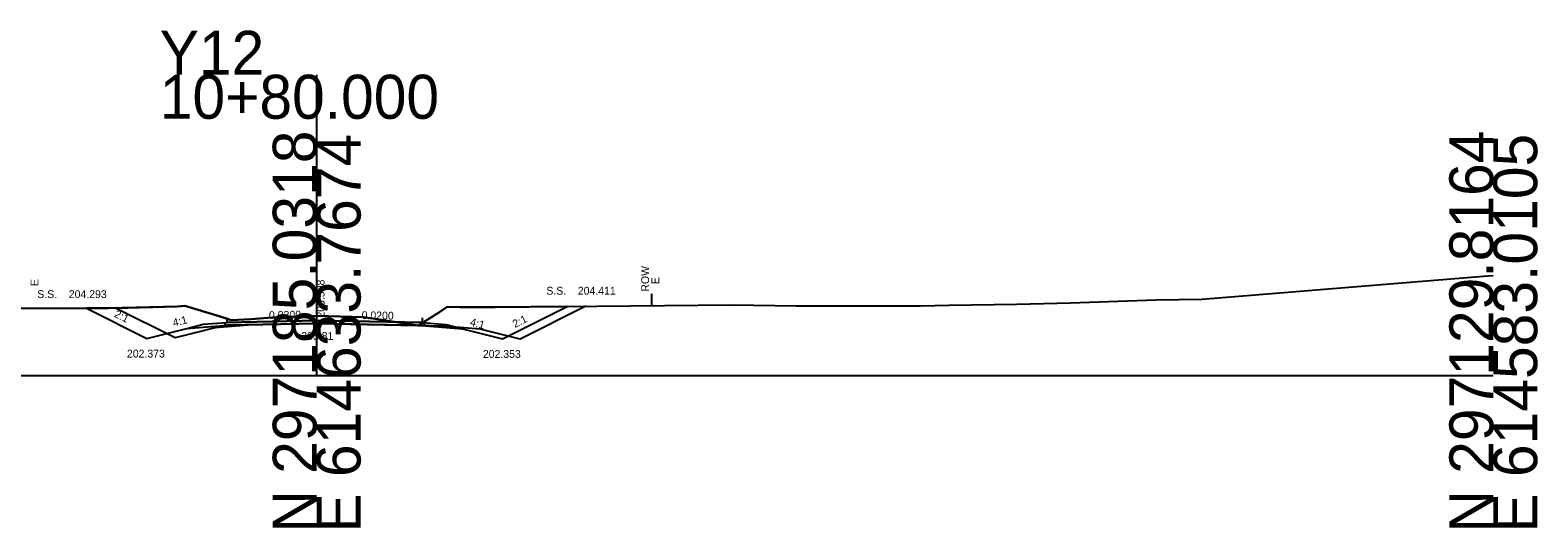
# Model space of a CAD drawing. Extents: x 517327 to 517505, y 114839 to 117367.
# Drawn here: x 517409.1 to 517505.2, y 116838.7 to 116870.4 of the extents above; entities that cross this region are included whole.
import ezdxf

# ---------------------------------------------------------------- set-up
doc = ezdxf.new("R2010")
doc.units = 0
for name, color, linetype in [('Exist XS Ground Line', 7, 'Continuous'), ('Old_Level_3', 7, 'Continuous'), ('Old_Level_5', 7, 'Continuous'), ('Old_Level_59', 7, 'Continuous'), ('Old_Level_63', 7, 'Continuous'), ('Prop XS Dump Level', 7, 'Continuous'), ('Prop XS Earthwork Shape', 7, 'Continuous'), ('Prop XS Elevation Labels', 7, 'Continuous'), ('Prop XS EOT Tick Mark', 7, 'Continuous'), ('Prop XS Exc Vertical Line 1', 7, 'Continuous'), ('Prop XS Exc Vertical Line 2', 7, 'Continuous'), ('Prop XS Finish Grade', 7, 'Continuous'), ('Prop XS Finish Grade Earthwork', 7, 'Continuous'), ('Prop XS Finish Grade Pavement', 7, 'Continuous'), ('Prop XS Hydro Elevations', 7, 'Continuous'), ('Prop XS Pvmt Edge Slope', 7, 'Continuous'), ('Prop XS Side Slope Text', 7, 'Continuous'), ('Prop XS Subgrade Earthwork', 7, 'Continuous'), ('Prop XS Suitable Common Exc Shape', 7, 'Continuous')]:
    doc.layers.add(name, color=color, linetype=linetype)

msp = doc.modelspace()

# ---------------------------------------------------------------- linework, layer by layer
at = {"layer": 'Exist XS Ground Line'}
for p, q in [((517483.816, 116853.243), (517501.736, 116854.705)), ((517501.736, 116854.705), (517502.365, 116854.751)), ((517471.995, 116852.914), (517475.409, 116853.002)), ((517475.409, 116853.002), (517480.879, 116853.183)), ((517480.879, 116853.183), (517483.816, 116853.243)), ((517404.83, 116852.668), (517414.081, 116852.656)), ((517414.081, 116852.656), (517418.494, 116852.776)), ((517418.494, 116852.776), (517418.955, 116852.803)), ((517418.955, 116852.803), (517421.159, 116852.154)), ((517421.159, 116852.154), (517421.913, 116851.895)), ((517421.913, 116851.895), (517423.177, 116851.971)), ((517423.177, 116851.971), (517424.538, 116852.068)), ((517424.538, 116852.068), (517426.792, 116852.151)), ((517426.792, 116852.151), (517427.456, 116852.176)), ((517427.456, 116852.176), (517428.114, 116852.159)), ((517428.114, 116852.159), (517430.36, 116852.093)), ((517430.36, 116852.093), (517431.779, 116851.873)), ((517433.833, 116851.562), (517435.188, 116852.414)), ((517435.188, 116852.414), (517435.691, 116852.74)), ((517435.691, 116852.74), (517436.514, 116852.716)), ((517436.514, 116852.716), (517438.736, 116852.734)), ((517438.736, 116852.734), (517453.851, 116852.871)), ((517453.851, 116852.871), (517457.919, 116852.819)), ((517457.919, 116852.819), (517465.86, 116852.803)), ((517465.86, 116852.803), (517467.658, 116852.851)), ((517467.658, 116852.851), (517471.995, 116852.914)), ((517431.779, 116851.873), (517433.833, 116851.562))]:
    msp.add_line(p, q, dxfattribs=at)
at = {"layer": 'Old_Level_63'}
for p, q in [((517427.365, 116848.365), (517427.365, 116867.524)), ((517352.365, 116848.365), (517427.365, 116848.365)), ((517427.365, 116848.365), (517502.365, 116848.365))]:
    msp.add_line(p, q, dxfattribs=at)
at = {"layer": 'Prop XS Dump Level'}
for p, q in [((517421.631, 116851.758), (517427.365, 116851.873)), ((517427.365, 116851.873), (517434.119, 116851.738))]:
    msp.add_line(p, q, dxfattribs=at)
at = {"layer": 'Prop XS Earthwork Shape'}
for points in [[(517412.692, 116852.658), (517416.531, 116850.738), (517419.082, 116851.376), (517420.131, 116851.46), (517421.437, 116851.564), (517421.631, 116851.568), (517427.365, 116851.683), (517433.833, 116851.562), (517431.779, 116851.873), (517430.36, 116852.093), (517428.114, 116852.159), (517427.456, 116852.176), (517426.792, 116852.151), (517424.538, 116852.068), (517423.177, 116851.971), (517421.913, 116851.895), (517421.159, 116852.154), (517418.955, 116852.803), (517418.494, 116852.776), (517414.081, 116852.656)], [(517436.668, 116851.355), (517439.219, 116850.718), (517443.335, 116852.776), (517438.736, 116852.734), (517436.514, 116852.716), (517435.691, 116852.74), (517435.188, 116852.414), (517433.833, 116851.562), (517434.119, 116851.548), (517434.313, 116851.544), (517435.619, 116851.439)]]:
    msp.add_lwpolyline(points, close=True, dxfattribs=at)
at = {"layer": 'Prop XS EOT Tick Mark'}
for p, q in [((517421.631, 116852.063), (517421.631, 116851.758)), ((517434.119, 116851.738), (517434.119, 116852.042))]:
    msp.add_line(p, q, dxfattribs=at)
at = {"layer": 'Prop XS Exc Vertical Line 1'}
msp.add_line((517448.701, 116853.574), (517448.701, 116852.824), dxfattribs=at)
at = {"layer": 'Prop XS Exc Vertical Line 2'}
msp.add_line((517448.701, 116853.574), (517448.701, 116852.824), dxfattribs=at)
at = {"layer": 'Prop XS Finish Grade'}
for p, q in [((517419.082, 116851.376), (517420.131, 116851.638)), ((517420.131, 116851.638), (517421.631, 116851.758)), ((517434.119, 116851.738), (517435.619, 116851.618)), ((517435.619, 116851.618), (517436.668, 116851.355))]:
    msp.add_line(p, q, dxfattribs=at)
at = {"layer": 'Prop XS Finish Grade Earthwork'}
for p, q in [((517412.692, 116852.658), (517416.531, 116850.738)), ((517439.219, 116850.718), (517443.335, 116852.776)), ((517416.531, 116850.738), (517419.082, 116851.376)), ((517436.668, 116851.355), (517439.219, 116850.718))]:
    msp.add_line(p, q, dxfattribs=at)
at = {"layer": 'Prop XS Finish Grade Pavement'}
for p, q in [((517427.365, 116851.873), (517421.631, 116851.758)), ((517434.119, 116851.738), (517427.365, 116851.873))]:
    msp.add_line(p, q, dxfattribs=at)
at = {"layer": 'Prop XS Pvmt Edge Slope'}
for p, q in [((517421.437, 116851.564), (517421.631, 116851.758)), ((517434.119, 116851.738), (517434.313, 116851.544))]:
    msp.add_line(p, q, dxfattribs=at)
at = {"layer": 'Prop XS Subgrade Earthwork'}
for p, q in [((517419.082, 116851.376), (517420.131, 116851.46)), ((517420.131, 116851.46), (517421.437, 116851.564)), ((517421.437, 116851.564), (517421.631, 116851.568)), ((517427.365, 116851.683), (517421.631, 116851.568)), ((517434.119, 116851.548), (517427.365, 116851.683)), ((517434.119, 116851.548), (517434.313, 116851.544)), ((517434.313, 116851.544), (517435.619, 116851.439)), ((517435.619, 116851.439), (517436.668, 116851.355))]:
    msp.add_line(p, q, dxfattribs=at)
at = {"layer": 'Prop XS Suitable Common Exc Shape'}
for points in [[(517433.833, 116851.562), (517427.365, 116851.683), (517423.44, 116851.604), (517423.246, 116851.6), (517421.94, 116851.496), (517420.891, 116851.412), (517418.34, 116850.774), (517414.551, 116852.669), (517418.494, 116852.776), (517418.955, 116852.803), (517421.159, 116852.154), (517421.913, 116851.895), (517423.177, 116851.971), (517424.538, 116852.068), (517426.792, 116852.151), (517427.456, 116852.176), (517428.114, 116852.159), (517430.36, 116852.093), (517431.779, 116851.873)], [(517438.736, 116852.734), (517444.517, 116852.786), (517440.335, 116850.695), (517437.784, 116851.333), (517436.735, 116851.417), (517435.429, 116851.521), (517435.235, 116851.525), (517433.833, 116851.562), (517435.188, 116852.414), (517435.691, 116852.74), (517436.514, 116852.716)]]:
    msp.add_lwpolyline(points, close=True, dxfattribs=at)

# ---------------------------------------------------------------- texts
at = {"layer": 'Old_Level_3'}
for rotation, p in [(14.03624, (517418.258, 116851.479)), (345.96376, (517437.107, 116851.555))]:
    msp.add_text('4:1', height=0.5, rotation=rotation, dxfattribs=at).set_placement(p)
at = {"layer": 'Old_Level_5'}
for rotation, p in [(1.14575, (517424.33, 116851.964)), (358.85423, (517430.227, 116851.968))]:
    msp.add_text('0.0200', height=0.5, rotation=rotation, dxfattribs=at).set_placement(p)
at = {"layer": 'Old_Level_59'}
msp.add_text(' 203.508', height=0.5, rotation=90, dxfattribs=at).set_placement((517427.865, 116851.873))
msp.add_text(' 203.508', height=0.5, rotation=90, dxfattribs=at).set_placement((517427.865, 116851.873))
msp.add_text(' 203.508', height=0.5, rotation=90, dxfattribs=at).set_placement((517427.865, 116851.873))
msp.add_text('203.81', height=0.5, dxfattribs=at).set_placement((517426.384, 116850.641))
at = {"layer": 'Old_Level_63'}
for s, p in [('Y12', (517417.362, 116867.524)), ('10+80.000', (517417.365, 116864.724))]:
    msp.add_text(s, height=2.8, dxfattribs=at).set_placement(p)
for s, p in [('N 297185.0318', (517427.365, 116838.365)), ('E 614633.7674', (517430.165, 116838.365)), ('N 297129.8164', (517502.365, 116838.365)), ('E 614583.0105', (517505.165, 116838.365))]:
    msp.add_text(s, height=2.8, rotation=90, dxfattribs=at).set_placement(p)
at = {"layer": 'Prop XS Elevation Labels'}
for p in [(517420.131, 116851.626), (517435.619, 116851.605)]:
    msp.add_text('Case1', height=0.0122, dxfattribs=at).set_placement(p)
at = {"layer": 'Prop XS Exc Vertical Line 1'}
for p in [(517409.627, 116854.07), (517449.203, 116854.186)]:
    msp.add_text('E', height=0.5, rotation=90, dxfattribs=at).set_placement(p)
at = {"layer": 'Prop XS Exc Vertical Line 2'}
msp.add_text('ROW', height=0.5, rotation=90, dxfattribs=at).set_placement((517448.552, 116853.712))
at = {"layer": 'Prop XS Hydro Elevations'}
for s, p in [('S.S.    204.411', (517442.006, 116853.522)), ('S.S.    204.293', (517409.558, 116853.303))]:
    msp.add_text(s, height=0.5, dxfattribs=at).set_placement(p)
at = {"layer": 'Prop XS Side Slope Text'}
for rotation, p in [(333.43495, (517414.416, 116852.131)), (26.56505, (517440.006, 116851.393))]:
    msp.add_text('2:1', height=0.5, rotation=rotation, dxfattribs=at).set_placement(p)
for s, p in [('202.373', (517415.272, 116849.518)), ('202.353', (517437.96, 116849.497))]:
    msp.add_text(s, height=0.5, dxfattribs=at).set_placement(p)

doc.saveas('drawing.dxf')
